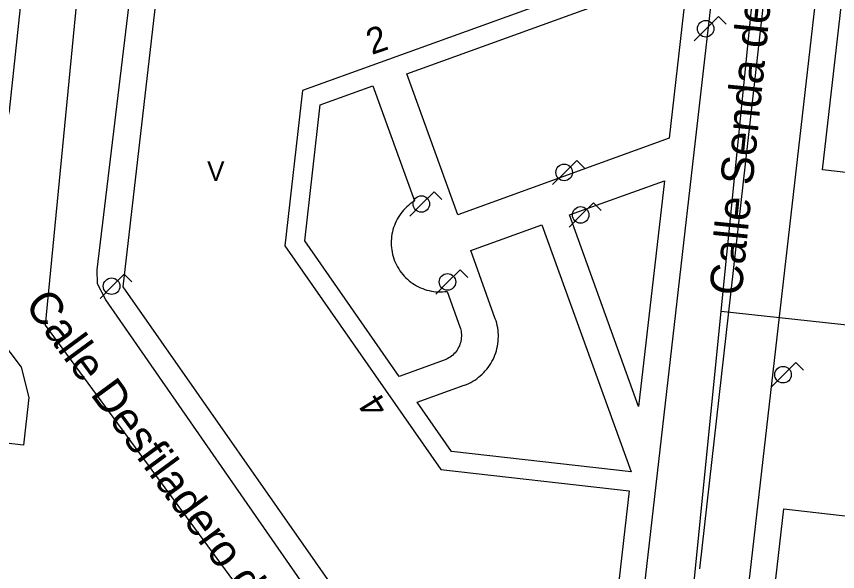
# Model space of a CAD drawing. Extents: x 282771 to 285132, y 4823109 to 4825496.
# Drawn here: x 283007.8 to 283071.1, y 4823915.7 to 4823958.4 of the extents above; entities that cross this region are included whole.
import ezdxf

# ---------------------------------------------------------------- set-up
doc = ezdxf.new("R2010")
doc.units = 0
for name, color, linetype in [('ACERA-BORDILLO', 7, 'Continuous'), ('BORDILLO', 7, 'Continuous'), ('CALLE-EJE', 7, 'Continuous'), ('CALLE-TEXTO', 7, 'Continuous'), ('EDIFICIO', 7, 'Continuous'), ('FAROLA', 7, 'Continuous'), ('NUM-PORTAL', 7, 'Continuous'), ('SENAL-VIARIA', 7, 'Continuous'), ('TXT-ALTURA-EDIFICIO', 7, 'Continuous'), ('ZONA-VERDE', 7, 'Continuous')]:
    doc.layers.add(name, color=color, linetype=linetype)

msp = doc.modelspace()

# ---------------------------------------------------------------- linework, layer by layer
at = {"layer": 'ACERA-BORDILLO'}
for points in [[(283138.869, 4823898.205), (283065.348, 4823906.606), (283064.99, 4823906.681), (283064.633, 4823906.83), (283064.461, 4823906.933), (283064.298, 4823907.055), (283064.146, 4823907.194), (283064.01, 4823907.349), (283063.889, 4823907.517), (283063.788, 4823907.696), (283063.706, 4823907.883), (283063.644, 4823908.073), (283063.58, 4823908.455), (283063.588, 4823908.821), (283072.21, 4823984.19)], [(283063.245, 4823976.233), (283055.67, 4823910.005)], [(283055.67, 4823910.005), (283055.595, 4823909.648), (283055.447, 4823909.291), (283055.223, 4823908.956), (283054.929, 4823908.668), (283054.583, 4823908.446), (283054.207, 4823908.302), (283053.826, 4823908.237), (283053.462, 4823908.244), (283035.063, 4823910.289), (283033.976, 4823910.497), (283033.014, 4823910.897), (283032.408, 4823911.371), (283031.905, 4823911.869), (283014.726, 4823936.6), (283014.076, 4823937.823), (283014.052, 4823938.898), (283017.099, 4823964.284)], [(283003.645, 4823937.384), (283008.189, 4823931.405), (283008.783, 4823929.069), (283008.369, 4823925.415), (283004.149, 4823925.895), (282996.079, 4823854.796), (283043.693, 4823849.222), (283046.052, 4823868.847), (283051.777, 4823868.21), (283052.18, 4823868.088), (283052.416, 4823868.016), (283052.638, 4823867.861), (283052.933, 4823867.624), (283053.295, 4823867.276), (283053.537, 4823866.967), (283072.621, 4823839.523), (283073.298, 4823838.878), (283074.171, 4823838.197), (283075.118, 4823837.59), (283076.301, 4823837.176), (283077.754, 4823836.86), (283264.587, 4823815.706)]]:
    msp.add_lwpolyline(points, dxfattribs=at)
at = {"layer": 'BORDILLO'}
msp.add_lwpolyline([(283008.453, 4823962.255), (283007.273, 4823951.139), (283007.181, 4823950.784), (283006.979, 4823950.458), (283006.688, 4823950.208), (283006.351, 4823950.063), (283005.987, 4823950.022), (283005.61, 4823950.094), (283005.273, 4823950.276), (283005.017, 4823950.538), (282998.774, 4823959.168)], dxfattribs=at)
at = {"layer": 'CALLE-EJE'}
for points in [[(283062.109, 4823935.715), (283068.049, 4823994.734)], [(283058.898, 4823903.605), (283030.509, 4823906.885), (283010.077, 4823934.649), (283013.979, 4823974.894)], [(283062.109, 4823935.715), (283094.035, 4823932.261), (283097.918, 4823956.455), (283150.661, 4823951.611)], [(283058.898, 4823903.605), (283062.109, 4823935.715)]]:
    msp.add_lwpolyline(points, dxfattribs=at)
at = {"layer": 'EDIFICIO'}
for points in [[(283084.296, 4823966.654), (283081.849, 4823945.245), (283069.919, 4823946.605), (283073.899, 4823981.384), (283147.388, 4824007.944), (283151.368, 4824007.494), (283145.908, 4823959.804), (283124.058, 4823962.304), (283126.968, 4823987.804), (283084.979, 4823972.624), (283084.296, 4823966.654)], [(283055.019, 4823921.885), (283053.659, 4823909.955), (283033.789, 4823912.235), (283016.059, 4823937.595), (283018.789, 4823961.464), (283057.099, 4823975.314), (283061.079, 4823974.854), (283059.779, 4823963.514), (283029.869, 4823952.705), (283028.499, 4823940.745), (283040.519, 4823923.535), (283055.019, 4823921.885)], [(283120.815, 4823933.964), (283122.688, 4823950.385), (283144.548, 4823947.885), (283139.098, 4823900.195), (283065.579, 4823908.595), (283066.939, 4823920.515), (283118.608, 4823914.615), (283120.815, 4823933.964)]]:
    msp.add_lwpolyline(points, dxfattribs=at)
at = {"layer": 'FAROLA'}
for p, q in [((283061.899, 4823958.395), (283060.959, 4823957.465)), ((283062.489, 4823957.805), (283061.899, 4823958.395)), ((283060.959, 4823957.465), (283060.029, 4823956.525)), ((283050.999, 4823947.335), (283050.059, 4823946.405)), ((283051.589, 4823946.745), (283050.999, 4823947.335)), ((283050.059, 4823946.405), (283049.129, 4823945.465)), ((283039.999, 4823944.905), (283039.059, 4823943.975)), ((283040.589, 4823944.315), (283039.999, 4823944.905)), ((283039.059, 4823943.975), (283038.129, 4823943.035)), ((283052.269, 4823944.065), (283051.329, 4823943.135)), ((283052.859, 4823943.475), (283052.269, 4823944.065)), ((283051.329, 4823943.135), (283050.399, 4823942.195)), ((283016.139, 4823938.575), (283015.199, 4823937.645)), ((283016.729, 4823937.985), (283016.139, 4823938.575)), ((283042.009, 4823938.905), (283041.069, 4823937.975)), ((283042.599, 4823938.315), (283042.009, 4823938.905)), ((283041.069, 4823937.975), (283040.139, 4823937.035)), ((283015.199, 4823937.645), (283014.269, 4823936.705)), ((283067.859, 4823931.765), (283066.919, 4823930.835)), ((283068.449, 4823931.175), (283067.859, 4823931.765)), ((283066.919, 4823930.835), (283065.989, 4823929.895))]:
    msp.add_line(p, q, dxfattribs=at)
for centre in [(283060.919, 4823957.465), (283050.019, 4823946.405), (283039.019, 4823943.975), (283051.289, 4823943.135), (283041.029, 4823937.975), (283015.159, 4823937.645)]:
    msp.add_circle(centre, 0.637, dxfattribs=at)
msp.add_ellipse((283066.879, 4823930.835), major_axis=(0.621, -0.145), ratio=0.99999, dxfattribs=at)
at = {"layer": 'SENAL-VIARIA'}
msp.add_lwpolyline([(283067.512, 4823978.446), (283060.438, 4823915.888)], dxfattribs=at)
at = {"layer": 'ZONA-VERDE'}
for p, q in [((283037.901, 4823954.006), (283059.574, 4823961.835)), ((283059.574, 4823961.835), (283058.11, 4823949.031)), ((283041.823, 4823943.148), (283037.901, 4823954.006)), ((283031.233, 4823951.597), (283035.291, 4823953.063)), ((283035.291, 4823953.063), (283038.491, 4823944.207)), ((283030.033, 4823941.127), (283031.233, 4823951.597)), ((283058.11, 4823949.031), (283041.823, 4823943.148)), ((283050.424, 4823943.129), (283057.737, 4823945.77)), ((283057.737, 4823945.77), (283055.749, 4823928.387)), ((283038.491, 4823944.207), (283038.447, 4823944.179)), ((283037.773, 4823943.632), (283037.655, 4823943.505)), ((283037.898, 4823943.754), (283037.773, 4823943.632)), ((283038.027, 4823943.869), (283037.898, 4823943.754)), ((283038.163, 4823943.979), (283038.027, 4823943.869)), ((283038.302, 4823944.082), (283038.163, 4823943.979)), ((283038.447, 4823944.179), (283038.302, 4823944.082)), ((283037.242, 4823942.946), (283037.156, 4823942.795)), ((283037.336, 4823943.093), (283037.242, 4823942.946)), ((283037.436, 4823943.235), (283037.336, 4823943.093)), ((283037.542, 4823943.372), (283037.436, 4823943.235)), ((283037.655, 4823943.505), (283037.542, 4823943.372)), ((283055.749, 4823928.387), (283050.424, 4823943.129)), ((283036.939, 4823942.321), (283036.882, 4823942.157)), ((283037.004, 4823942.482), (283036.939, 4823942.321)), ((283037.077, 4823942.64), (283037.004, 4823942.482)), ((283037.156, 4823942.795), (283037.077, 4823942.64)), ((283042.822, 4823940.383), (283048.308, 4823942.364)), ((283048.308, 4823942.364), (283055.174, 4823923.357)), ((283036.79, 4823941.821), (283036.756, 4823941.651)), ((283036.832, 4823941.99), (283036.79, 4823941.821)), ((283036.882, 4823942.157), (283036.832, 4823941.99)), ((283037.311, 4823930.703), (283030.033, 4823941.127)), ((283036.7, 4823941.132), (283036.698, 4823940.958)), ((283036.711, 4823941.306), (283036.7, 4823941.132)), ((283036.729, 4823941.479), (283036.711, 4823941.306)), ((283036.756, 4823941.651), (283036.729, 4823941.479)), ((283036.698, 4823940.958), (283036.703, 4823940.784)), ((283036.703, 4823940.784), (283036.717, 4823940.611)), ((283036.717, 4823940.611), (283036.738, 4823940.439)), ((283036.738, 4823940.439), (283036.767, 4823940.267)), ((283036.767, 4823940.267), (283036.804, 4823940.097)), ((283036.804, 4823940.097), (283036.849, 4823939.929)), ((283036.849, 4823939.929), (283036.902, 4823939.763)), ((283036.902, 4823939.763), (283036.962, 4823939.6)), ((283044.716, 4823935.139), (283042.822, 4823940.383)), ((283036.962, 4823939.6), (283037.03, 4823939.44)), ((283037.03, 4823939.44), (283037.105, 4823939.283)), ((283037.105, 4823939.283), (283037.187, 4823939.13)), ((283037.187, 4823939.13), (283037.276, 4823938.981)), ((283037.276, 4823938.981), (283037.372, 4823938.835)), ((283037.372, 4823938.835), (283037.474, 4823938.695)), ((283037.474, 4823938.695), (283037.583, 4823938.559)), ((283037.583, 4823938.559), (283037.698, 4823938.429)), ((283037.698, 4823938.429), (283037.819, 4823938.303)), ((283037.819, 4823938.303), (283037.945, 4823938.184)), ((283037.945, 4823938.184), (283038.077, 4823938.07)), ((283038.077, 4823938.07), (283038.213, 4823937.963)), ((283038.213, 4823937.963), (283038.355, 4823937.862)), ((283038.355, 4823937.862), (283038.501, 4823937.768)), ((283038.501, 4823937.768), (283038.651, 4823937.68)), ((283038.651, 4823937.68), (283038.806, 4823937.6)), ((283038.806, 4823937.6), (283038.963, 4823937.527)), ((283038.963, 4823937.527), (283039.124, 4823937.46)), ((283039.124, 4823937.46), (283039.288, 4823937.402)), ((283039.288, 4823937.402), (283039.454, 4823937.351)), ((283039.454, 4823937.351), (283039.623, 4823937.308)), ((283039.623, 4823937.308), (283039.793, 4823937.272)), ((283039.793, 4823937.272), (283039.964, 4823937.245)), ((283039.964, 4823937.245), (283040.137, 4823937.225)), ((283040.659, 4823937.214), (283040.832, 4823937.226)), ((283040.832, 4823937.226), (283041.005, 4823937.247)), ((283041.005, 4823937.247), (283041.99, 4823934.52)), ((283040.137, 4823937.225), (283040.311, 4823937.213)), ((283040.311, 4823937.213), (283040.485, 4823937.21)), ((283040.485, 4823937.21), (283040.659, 4823937.214)), ((283044.773, 4823934.97), (283044.716, 4823935.139)), ((283044.823, 4823934.798), (283044.773, 4823934.97)), ((283044.864, 4823934.624), (283044.823, 4823934.798)), ((283041.99, 4823934.52), (283042.025, 4823934.4)), ((283042.025, 4823934.4), (283042.052, 4823934.296)), ((283042.052, 4823934.296), (283042.077, 4823934.172)), ((283042.077, 4823934.172), (283042.094, 4823934.047)), ((283044.898, 4823934.448), (283044.864, 4823934.624)), ((283044.924, 4823934.271), (283044.898, 4823934.448)), ((283044.942, 4823934.093), (283044.924, 4823934.271)), ((283044.952, 4823933.915), (283044.942, 4823934.093)), ((283042.083, 4823933.542), (283042.06, 4823933.418)), ((283042.098, 4823933.668), (283042.083, 4823933.542)), ((283042.094, 4823934.047), (283042.103, 4823933.921)), ((283042.104, 4823933.794), (283042.098, 4823933.668)), ((283042.103, 4823933.921), (283042.104, 4823933.794)), ((283044.934, 4823933.379), (283044.948, 4823933.557)), ((283044.948, 4823933.557), (283044.954, 4823933.736)), ((283044.954, 4823933.736), (283044.952, 4823933.915)), ((283041.832, 4823932.831), (283041.765, 4823932.724)), ((283041.892, 4823932.942), (283041.832, 4823932.831)), ((283041.946, 4823933.057), (283041.892, 4823932.942)), ((283041.991, 4823933.175), (283041.946, 4823933.057)), ((283042.03, 4823933.295), (283041.991, 4823933.175)), ((283042.06, 4823933.418), (283042.03, 4823933.295)), ((283044.799, 4823932.677), (283044.845, 4823932.85)), ((283044.845, 4823932.85), (283044.882, 4823933.025)), ((283044.882, 4823933.025), (283044.912, 4823933.201)), ((283044.912, 4823933.201), (283044.934, 4823933.379)), ((283041.234, 4823932.188), (283041.127, 4823932.12)), ((283041.336, 4823932.263), (283041.234, 4823932.188)), ((283041.433, 4823932.344), (283041.336, 4823932.263)), ((283041.525, 4823932.431), (283041.433, 4823932.344)), ((283041.611, 4823932.523), (283041.525, 4823932.431)), ((283041.691, 4823932.621), (283041.611, 4823932.523)), ((283041.765, 4823932.724), (283041.691, 4823932.621)), ((283044.541, 4823932.01), (283044.617, 4823932.173)), ((283044.617, 4823932.173), (283044.685, 4823932.338)), ((283044.685, 4823932.338), (283044.746, 4823932.506)), ((283044.746, 4823932.506), (283044.799, 4823932.677)), ((283040.784, 4823931.958), (283037.311, 4823930.703)), ((283040.902, 4823932.005), (283040.784, 4823931.958)), ((283041.016, 4823932.059), (283040.902, 4823932.005)), ((283041.127, 4823932.12), (283041.016, 4823932.059)), ((283044.169, 4823931.4), (283044.272, 4823931.546)), ((283044.272, 4823931.546), (283044.369, 4823931.697)), ((283044.369, 4823931.697), (283044.459, 4823931.852)), ((283044.459, 4823931.852), (283044.541, 4823932.01)), ((283043.694, 4823930.866), (283043.822, 4823930.992)), ((283043.822, 4823930.992), (283043.944, 4823931.123)), ((283043.944, 4823931.123), (283044.06, 4823931.259)), ((283044.06, 4823931.259), (283044.169, 4823931.4)), ((283042.824, 4823930.244), (283042.98, 4823930.331)), ((283042.98, 4823930.331), (283043.132, 4823930.425)), ((283043.132, 4823930.425), (283043.28, 4823930.526)), ((283043.28, 4823930.526), (283043.423, 4823930.633)), ((283043.423, 4823930.633), (283043.561, 4823930.747)), ((283043.561, 4823930.747), (283043.694, 4823930.866)), ((283038.7, 4823928.713), (283042.313, 4823930.018)), ((283042.313, 4823930.018), (283042.334, 4823930.026)), ((283042.334, 4823930.026), (283042.5, 4823930.091)), ((283042.5, 4823930.091), (283042.664, 4823930.164)), ((283042.664, 4823930.164), (283042.824, 4823930.244)), ((283041.343, 4823924.927), (283038.7, 4823928.713)), ((283055.174, 4823923.357), (283041.343, 4823924.927))]:
    msp.add_line(p, q, dxfattribs=at)

# ---------------------------------------------------------------- texts
at = {"layer": 'CALLE-TEXTO'}
for s, rotation, p in [('Calle Senda del Arcediano', 84.28981, (283063.672, 4823936.855)), ('Calle Desfiladero de los Beyos', 306.34972, (283008.401, 4823936.221))]:
    msp.add_text(s, height=2.5, rotation=rotation, dxfattribs=at).set_placement(p)
at = {"layer": 'NUM-PORTAL'}
for s, rotation, p in [('2', 18.85004, (283035.196, 4823955.438)), ('4', 121.81973, (283036.557, 4823928.301))]:
    msp.add_text(s, height=2, rotation=rotation, dxfattribs=at).set_placement(p)
at = {"layer": 'TXT-ALTURA-EDIFICIO'}
msp.add_text('V', height=1.5, rotation=0.00004, dxfattribs=at).set_placement((283022.52, 4823945.755))

doc.saveas('drawing.dxf')
